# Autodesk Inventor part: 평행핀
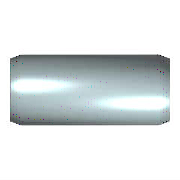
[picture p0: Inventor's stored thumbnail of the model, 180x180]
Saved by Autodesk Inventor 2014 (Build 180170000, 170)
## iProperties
IsCustomPart: 0
Created: 2009-02
Part Number: 평행핀
Material: 강, 연강
Description: 평행 핀
Document SubType Name: Modeling
Standard: KS B 1320
Designer: KYOUNG IL JANG
Standards Organization: KS
Language: ko-KR
Size Designation: B 5 x  20
Categories: <MemberInstance><Categories><Category DisplayName="조임쇠" InternalName="e4da775c-781d-43d5-af7c-5136215cf5a6" Mnemonic="FSTN"><Category DisplayName="핀" InternalNa
Density: 1 g/cm^3
Appearance: 강철
Author: KYOUNG IL JANG
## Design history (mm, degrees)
sketch "스케치"
  geometry: C1 r 2.5 at (0, 0); 1 further point
  constraints: 1 centre point, 1 coincident
  dimensions: "d1" = 5 diameter of C1 (= NND)
extrude "본체" new body sketch "스케치" distance "d2" = 20 (= NLG); taper "d3" = 0 deg
chamfer "스케치2" distance "d8" = 0.8 (= PHH); stored, may be unused: angle "d9" = 15 deg (= FAWI), second distance "d12" = 0.8 (= PHH)
node "작업 평면1"
body "Solid1"
chamfer "모따기1" distance "d4" = 0.8 (= PHH); stored, may be unused: angle "d5" = 15 deg (= FAWI), second distance "d11" = 0.8 (= PHH)
other parameters: "NND" = 5 [user parameter; used in 1 equation term], "NLG" = 20 [user parameter; used in 1 equation term], "PHH" = 0.8 [user parameter; used in 4 equation terms], "FAWI" = 15 deg [user parameter; used in 2 equation terms], "d13" = 0, "d15" = 0, "d16" = 0, "KAH" = 0.63 [user parameter]
